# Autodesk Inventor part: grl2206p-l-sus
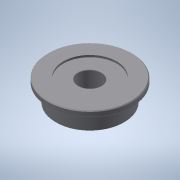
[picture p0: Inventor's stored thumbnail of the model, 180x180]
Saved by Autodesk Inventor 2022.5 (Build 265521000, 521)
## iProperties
Created: 2016-12
Part Number: grl2206p-l-sus
Material: 一般
Document SubType Name: Modeling
Designer: imaocorp
Density: 1 g/cm^3
Appearance: 既定
Author: imaocorp
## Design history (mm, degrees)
node "grl2206p-l-sus.x_t1"
node "grl2206p-l-sus"
node "Base1"
